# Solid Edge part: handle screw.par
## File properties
Title: Handle Screw
Author: Robert a Rhodes jr
Template: Normal.par
Last saved by: TIET
Revision: 13
Application: Solid Edge
Accuracy: 0.99
Material: aluminum
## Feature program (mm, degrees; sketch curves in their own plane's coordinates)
sketch for "unnamed Protrusion 1" plane through (0, 0, 0) normal (0, -1, 0) x-axis (1, 0, 0)
  circle centre (0, 0) radius 7.5
extrude "unnamed Protrusion 1" add finite 14 along +normal
sketch for "Hole_1" plane through (0, -14, 0) normal (0, -1, 0) x-axis (1, 0, 0)
  hole centre (0, 0) bore radius 4
hole "Hole_1" diameter 8 finite  VBottomAngle = 120 deg
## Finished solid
Body 1: solid body, 5 faces, 4 edges, 1 vertex.
  Faces by surface: cylinder 2, plane 2, cone 1
  Edges by curve: circle 4
Bounding box of the edges (mm): 15.000 x 14.000 x 15.000, from (-7.5, -14, -7.5) to (7.5, 0, 7.5).
Cylindrical faces by radius (mm): R4 x1, R7.5 x1
Conical faces (half-angle, radius in mm at the cone's reference point): 60 deg R4 x1
Planar faces by outward normal: +y 1, -y 1
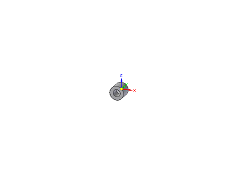
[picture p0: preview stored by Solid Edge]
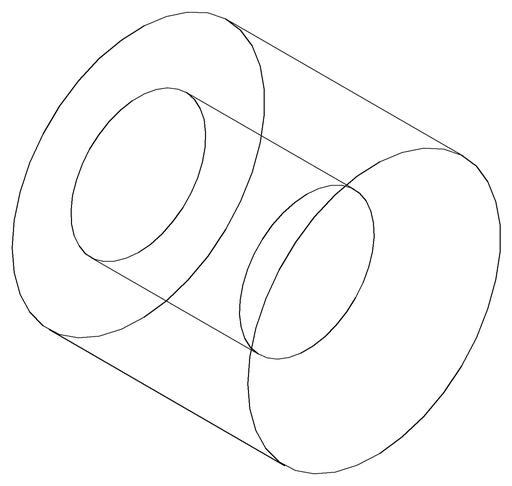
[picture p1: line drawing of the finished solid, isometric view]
